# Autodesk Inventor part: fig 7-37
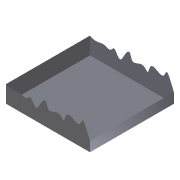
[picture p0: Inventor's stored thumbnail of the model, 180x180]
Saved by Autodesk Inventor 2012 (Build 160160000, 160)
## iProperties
Shininess: 64.0
Length Units: 11269
Angle Units: 11279
Time Units: 11290
Mass Units: 11283
Length Display Precision: 3
Angle Display Precision: 2
Compacted: True
Part Number: fig 7-37
Document SubType Name: Modeling
Created: 2002-12
Designer: deepak
Density: 1 g/cm^3
Material: Default
Density: 0.0
Volumn: 0.0
Area: 0.0
PropertySet Name: Model Information
Control State: 0
Master: False
Checked Out: False
Author: deepak
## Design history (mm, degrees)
sketch "Sketch1"
  geometry: L1 (-32.188, 30.089)-(27.812, 30.089); L2 (27.812, 30.089)-(27.812, -29.911); L3 (27.812, -29.911)-(-32.188, -29.911); L4 (-32.188, -29.911)-(-32.188, 30.089)
  constraints: 8 end point, 2 parallel, 1 horizontal, 1 perpendicular
  dimensions: "d0" = 60 distance of L1.start L1.end; "d1" = 60 distance of L3.end L1.start
extrude "Extrusion1" new body sketch "Sketch1" stored distance "d2" = 20; taper "d3" = 0 deg
sketch "Sketch2"
  geometry: 17 further points
  constraints: 17 other
extrude_surface "ExtrusionSrf1" sketch "Sketch2" dims "d4" = 70, "d5" = 0
split "Split1"
delete_face "Delete Face1"
node "Sketch5"
body "Srf1"
body "Srf2"
